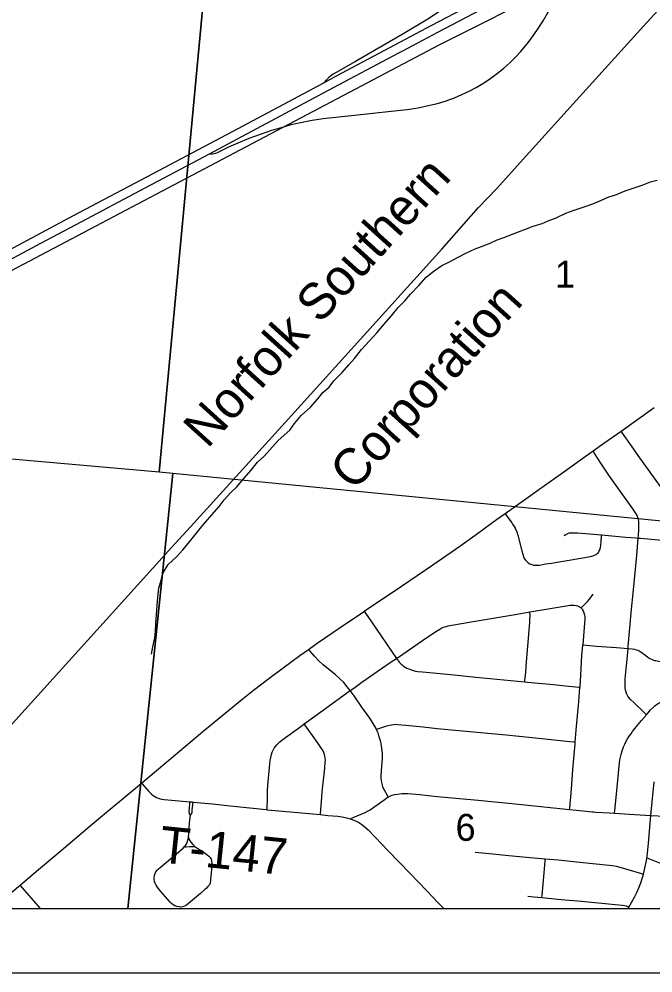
# Model space of a CAD drawing. Extents: x 831 to 1552, y 430 to 870.
# Drawn here: x 1297.11 to 1316.8, y 648.94 to 678.59 of the extents above; entities that cross this region are included whole.
import ezdxf

# ---------------------------------------------------------------- set-up
doc = ezdxf.new("R2010")
doc.units = 0
for name, color, linetype in [('GM_X_Corporation', 7, 'Continuous'), ('GM_X_County_Road', 7, 'Continuous'), ('GM_X_Interchange_Ramps', 7, 'Continuous'), ('GM_X_Interstate_Route', 7, 'Continuous'), ('GM_X_Minor_River', 7, 'Continuous'), ('GM_X_Rail_Line', 7, 'Continuous'), ('GM_X_Rail_Line_Text', 7, 'Continuous'), ('GM_X_Section_Text', 7, 'Continuous'), ('GM_X_State_Route', 7, 'Continuous'), ('GM_X_Township_Road', 7, 'Continuous'), ('GM_X_Township_Road_Text', 7, 'Continuous'), ('SH_Data', 7, 'Continuous')]:
    doc.layers.add(name, color=color, linetype=linetype)

msp = doc.modelspace()

# ---------------------------------------------------------------- linework, layer by layer
at = {"layer": 'GM_X_Corporation'}
msp.add_lwpolyline([(1250.766, 650.938), (1386.766, 650.938), (1386.766, 724.317)], dxfattribs=at)
for points in [[(1283.584, 686.544), (1303.37, 684.858), (1301.464, 664.502), (1281.807, 666.237)], [(1303.37, 684.858), (1323.531, 682.478), (1321.541, 662.548), (1301.887, 664.457), (1301.464, 664.502)], [(1280.498, 650.938), (1300.485, 650.938), (1301.887, 664.457), (1301.464, 664.502), (1281.807, 666.237)], [(1300.485, 650.938), (1320.907, 650.938), (1321.979, 662.503), (1321.541, 662.548), (1301.887, 664.457)]]:
    msp.add_lwpolyline(points, close=True, dxfattribs=at)
at = {"layer": 'GM_X_County_Road'}
msp.add_line((1315.814, 665.779), (1316.848, 666.513), dxfattribs=at)
for points in [[(1314.945, 665.163), (1315.28, 665.4), (1315.814, 665.779)], [(1312.208, 663.216), (1312.854, 663.671), (1313.258, 663.96), (1313.966, 664.464), (1314.622, 664.934), (1314.945, 665.163)], [(1307.827, 660.179), (1308.99, 660.963), (1309.967, 661.625), (1310.801, 662.203), (1311.351, 662.6), (1311.941, 663.027), (1312.208, 663.216)], [(1306.099, 658.994), (1306.369, 659.188), (1307.088, 659.676), (1307.807, 660.165), (1307.827, 660.179)], [(1300.908, 654.837), (1301.176, 655.06), (1301.506, 655.337), (1302.882, 656.497), (1304.028, 657.436), (1304.391, 657.722), (1304.865, 658.092), (1305.312, 658.426), (1305.832, 658.801), (1306.099, 658.994)], [(1297.137, 651.668), (1297.512, 651.984), (1298.414, 652.744), (1299.312, 653.508), (1299.703, 653.836), (1300.301, 654.33), (1300.908, 654.837)], [(1296.266, 650.938), (1296.609, 651.225), (1297.085, 651.624), (1297.137, 651.668)]]:
    msp.add_lwpolyline(points, dxfattribs=at)
at = {"layer": 'GM_X_Interchange_Ramps'}
msp.add_lwpolyline([(1316.766, 684.819), (1316.253, 684.266), (1315.369, 683.31), (1314.816, 682.723), (1314.381, 682.282), (1313.979, 681.895), (1313.477, 681.432), (1312.968, 680.979), (1312.401, 680.496), (1311.97, 680.143), (1311.432, 679.723), (1310.935, 679.352), (1310.48, 679.028), (1310.172, 678.821), (1309.805, 678.588), (1309.008, 678.109), (1307.562, 677.263), (1306.957, 676.925), (1306.87, 676.872), (1306.781, 676.807), (1306.736, 676.769), (1306.693, 676.73), (1306.652, 676.687), (1306.577, 676.607)], dxfattribs=at)
at = {"layer": 'GM_X_Interstate_Route'}
for points in [[(1296.221, 671.1), (1298.795, 672.482), (1301.269, 673.783), (1303.737, 675.096), (1306.577, 676.607), (1306.973, 676.818), (1309.934, 678.396), (1310.869, 678.886), (1311.642, 679.283), (1312.478, 679.693), (1313.096, 679.984), (1313.775, 680.291), (1314.453, 680.589), (1314.514, 680.616), (1315.029, 680.832), (1315.72, 681.109), (1316.416, 681.372), (1317.469, 681.748), (1318.641, 682.161), (1319.931, 682.613), (1320.991, 682.995), (1322.52, 683.559), (1323.315, 683.849), (1323.468, 683.902)], [(1308.905, 677.534), (1309.028, 677.6), (1310.125, 678.184), (1311.445, 678.879), (1312.057, 679.186), (1312.786, 679.534), (1313.002, 679.632)], [(1303.02, 674.4), (1303.6, 674.708), (1306.724, 676.375), (1308.905, 677.534)], [(1276.248, 660.164), (1276.827, 660.475), (1278.858, 661.553), (1281.437, 662.923), (1282.589, 663.534), (1284.234, 664.411), (1285.716, 665.197), (1288.513, 666.687), (1290.485, 667.742), (1290.978, 668.006), (1291.471, 668.27), (1291.819, 668.455), (1292.294, 668.707), (1293.889, 669.547), (1296.249, 670.798), (1297.783, 671.619), (1299.212, 672.373), (1300.69, 673.166), (1303.02, 674.4)]]:
    msp.add_lwpolyline(points, dxfattribs=at)
at = {"layer": 'GM_X_Minor_River'}
for points in [[(1305.524, 665.809), (1305.663, 666.019), (1305.871, 666.26), (1306.163, 666.522), (1306.387, 666.785), (1306.549, 666.981), (1306.741, 667.146), (1306.888, 667.341), (1307.149, 667.604), (1307.357, 667.837), (1307.527, 668.032), (1307.751, 668.318), (1307.997, 668.581), (1308.228, 668.829), (1308.444, 669.092), (1308.667, 669.355), (1308.883, 669.625), (1309.099, 669.828), (1309.276, 670.031), (1309.53, 670.309), (1309.754, 670.564), (1310.007, 670.759), (1310.244, 670.923), (1310.466, 671.034), (1310.756, 671.182), (1311.009, 671.316), (1311.284, 671.449), (1311.475, 671.515), (1311.749, 671.618), (1311.964, 671.722), (1312.17, 671.795), (1312.628, 671.972), (1312.849, 672.06), (1313.086, 672.149), (1313.36, 672.236), (1313.551, 672.317), (1313.795, 672.413), (1314.094, 672.554), (1314.33, 672.634), (1314.544, 672.708), (1314.734, 672.774), (1314.933, 672.847), (1315.208, 672.958), (1315.429, 673.061), (1315.62, 673.112), (1315.941, 673.245), (1316.254, 673.355), (1316.475, 673.428), (1316.727, 673.524), (1316.94, 673.582)], [(1301.226, 658.849), (1301.267, 659.076), (1301.323, 659.356), (1301.348, 659.56), (1301.359, 659.81), (1301.377, 660.053), (1301.396, 660.355), (1301.414, 660.62), (1301.448, 660.893), (1301.519, 661.142), (1301.582, 661.376), (1301.737, 661.632), (1302.012, 661.879), (1302.196, 662.089), (1302.357, 662.284), (1302.572, 662.546), (1302.733, 662.749), (1302.902, 662.951), (1303.094, 663.176), (1303.324, 663.439), (1303.477, 663.641), (1303.684, 663.866), (1303.875, 664.046), (1304.09, 664.308), (1304.32, 664.563), (1304.512, 664.811), (1304.719, 665.005), (1305.163, 665.485), (1305.524, 665.809)]]:
    msp.add_lwpolyline(points, dxfattribs=at)
at = {"layer": 'GM_X_Rail_Line'}
for points in [[(1261.527, 652.567), (1284.1, 664.037), (1310.179, 677.801), (1313.677, 679.557), (1320.635, 683.299), (1323.83, 685.434), (1326.948, 687.535)], [(1291.697, 650.938), (1294.966, 654.558), (1301.848, 662.157), (1302.434, 662.803), (1305.676, 666.376), (1310.245, 671.433), (1311.385, 672.727), (1311.952, 673.316), (1312.776, 674.235), (1314.625, 676.28), (1316.515, 678.363), (1317.75, 679.732), (1318.964, 681.068), (1319.334, 681.453), (1320.111, 682.215), (1320.633, 682.733), (1321.491, 683.396), (1322.009, 683.791), (1322.837, 684.376), (1324.039, 685.196), (1324.617, 685.605)]]:
    msp.add_lwpolyline(points, dxfattribs=at)
at = {"layer": 'GM_X_State_Route'}
for points in [[(1312.937, 677.87), (1313.086, 678.068), (1313.261, 678.324), (1313.392, 678.535), (1313.544, 678.805), (1313.772, 679.246), (1314.033, 679.763)], [(1303.02, 674.4), (1303.073, 674.396), (1303.12, 674.398), (1303.169, 674.406), (1303.222, 674.421), (1303.274, 674.441), (1303.629, 674.613), (1303.913, 674.74), (1304.258, 674.882), (1304.608, 675.013), (1304.962, 675.132), (1305.261, 675.221), (1305.603, 675.315), (1305.904, 675.381), (1306.213, 675.442), (1306.558, 675.497), (1307.532, 675.601), (1308.669, 675.723), (1309.164, 675.778), (1309.505, 675.829), (1309.87, 675.906), (1310.11, 675.966), (1310.347, 676.038), (1310.638, 676.143), (1310.867, 676.238), (1311.091, 676.343), (1311.31, 676.46), (1311.522, 676.587), (1311.729, 676.724), (1311.979, 676.907), (1312.172, 677.062), (1312.357, 677.227), (1312.534, 677.4), (1312.701, 677.583), (1312.9, 677.821), (1312.937, 677.87)], [(1276.248, 660.164), (1276.827, 660.475), (1278.858, 661.553), (1281.437, 662.923), (1282.589, 663.534), (1284.234, 664.411), (1285.716, 665.197), (1288.513, 666.687), (1290.485, 667.742), (1290.978, 668.006), (1291.471, 668.27), (1291.819, 668.455), (1292.294, 668.707), (1293.889, 669.547), (1296.249, 670.798), (1297.783, 671.619), (1299.212, 672.373), (1300.69, 673.166), (1303.02, 674.4)]]:
    msp.add_lwpolyline(points, dxfattribs=at)
at = {"layer": 'GM_X_Township_Road'}
for p, q in [((1316.742, 653.835), (1316.842, 654.882)), ((1297.771, 650.938), (1297.137, 651.668)), ((1316.03, 650.938), (1316.054, 650.979))]:
    msp.add_line(p, q, dxfattribs=at)
for points in [[(1317.442, 662.355), (1317.489, 662.868), (1317.504, 663.056), (1317.504, 663.184), (1317.499, 663.258), (1317.491, 663.325), (1317.477, 663.373), (1317.453, 663.439), (1317.43, 663.49), (1317.369, 663.594), (1317.265, 663.746), (1317.224, 663.802), (1316.719, 664.499), (1316.35, 665.024), (1316.136, 665.321), (1315.856, 665.719), (1315.814, 665.779)], [(1316.348, 662.455), (1316.354, 662.53), (1316.365, 662.716), (1316.369, 662.904), (1316.364, 662.968), (1316.352, 663.03), (1316.334, 663.092), (1316.31, 663.151), (1316.281, 663.207), (1316.182, 663.366), (1315.46, 664.375), (1315.184, 664.786), (1315.002, 665.074), (1314.945, 665.163)], [(1312.208, 663.216), (1312.243, 663.168), (1312.419, 662.924), (1312.445, 662.886), (1312.491, 662.814), (1312.52, 662.764), (1312.571, 662.652), (1312.603, 662.54), (1312.729, 662.056), (1312.784, 661.879), (1312.807, 661.822), (1312.84, 661.77), (1312.881, 661.724), (1312.929, 661.685), (1312.981, 661.652), (1313.038, 661.629), (1313.098, 661.614), (1313.16, 661.608), (1313.221, 661.61), (1313.283, 661.617), (1313.465, 661.649), (1313.649, 661.678), (1313.83, 661.707), (1314.135, 661.762), (1314.622, 661.841), (1314.804, 661.875), (1314.911, 661.897), (1314.97, 661.913), (1315.012, 661.931), (1315.043, 661.948), (1315.084, 661.981), (1315.109, 662.011), (1315.127, 662.036), (1315.156, 662.092), (1315.172, 662.162), (1315.185, 662.222), (1315.196, 662.345), (1315.207, 662.507), (1315.211, 662.554)], [(1314.05, 662.535), (1314.099, 662.566), (1314.14, 662.591), (1314.177, 662.605), (1314.208, 662.615), (1314.275, 662.621), (1314.337, 662.621), (1314.463, 662.614), (1315.087, 662.564), (1315.211, 662.554)], [(1315.211, 662.554), (1315.526, 662.528), (1315.965, 662.487), (1316.287, 662.459), (1316.348, 662.455)], [(1316.035, 659.024), (1316.039, 659.079), (1316.139, 660.246), (1316.189, 660.739), (1316.304, 661.912), (1316.348, 662.455)], [(1316.348, 662.455), (1316.414, 662.451), (1316.981, 662.4), (1317.442, 662.355)], [(1314.574, 660.29), (1314.654, 660.367), (1314.772, 660.486), (1314.823, 660.541), (1314.864, 660.593), (1314.899, 660.639), (1314.947, 660.707)], [(1312.984, 660.157), (1313.615, 660.267), (1314.105, 660.349), (1314.228, 660.364), (1314.291, 660.368), (1314.354, 660.367), (1314.418, 660.356), (1314.46, 660.345), (1314.508, 660.33), (1314.543, 660.311), (1314.574, 660.29)], [(1314.574, 660.29), (1314.594, 660.267), (1314.621, 660.227), (1314.637, 660.197), (1314.648, 660.165), (1314.661, 660.13), (1314.676, 660.066), (1314.684, 660.002), (1314.687, 659.937), (1314.679, 659.81), (1314.627, 659.138)], [(1307.827, 660.179), (1307.87, 660.117), (1308.057, 659.847), (1308.831, 658.713)], [(1308.831, 658.713), (1309.033, 658.848), (1309.646, 659.267), (1310.055, 659.548), (1310.178, 659.626), (1310.244, 659.66), (1310.296, 659.681), (1310.351, 659.7), (1310.438, 659.725), (1310.495, 659.736), (1310.554, 659.75), (1311.16, 659.849), (1312.585, 660.087), (1312.984, 660.157)], [(1312.824, 657.983), (1312.828, 658.023), (1312.852, 658.288), (1312.878, 658.609), (1312.914, 659.097), (1312.975, 659.829), (1312.98, 659.934), (1312.985, 660.048), (1312.984, 660.157)], [(1314.537, 657.814), (1314.539, 657.84), (1314.561, 658.196), (1314.6, 658.808), (1314.627, 659.138)], [(1314.627, 659.138), (1315.051, 659.097), (1315.67, 659.05), (1316.035, 659.024)], [(1307.399, 657.715), (1307.305, 657.831), (1307.194, 657.962), (1307.067, 658.087), (1306.93, 658.213), (1306.556, 658.514), (1306.42, 658.642), (1306.286, 658.781), (1306.141, 658.947), (1306.099, 658.994)], [(1316.603, 656.959), (1316.541, 657.02), (1316.496, 657.063), (1316.227, 657.32), (1316.102, 657.452), (1316.06, 657.5), (1316.026, 657.544), (1315.993, 657.605), (1315.968, 657.666), (1315.954, 657.725), (1315.942, 657.791), (1315.939, 657.868), (1315.939, 657.965), (1315.944, 658.08), (1315.977, 658.392), (1315.998, 658.577), (1316.035, 659.024)], [(1316.035, 659.024), (1316.164, 659.009), (1316.23, 658.997), (1316.283, 658.985), (1316.334, 658.968), (1316.374, 658.95), (1316.411, 658.931), (1316.459, 658.9), (1316.512, 658.861), (1316.583, 658.802), (1316.649, 658.75), (1316.707, 658.715), (1316.764, 658.688), (1316.805, 658.67), (1316.858, 658.653), (1316.898, 658.644), (1316.976, 658.633), (1317.073, 658.622), (1317.097, 658.62)], [(1307.399, 657.715), (1307.506, 657.791), (1307.762, 657.976), (1308.367, 658.396), (1308.673, 658.608), (1308.831, 658.713)], [(1308.831, 658.713), (1308.897, 658.632), (1308.934, 658.589), (1308.985, 658.535), (1309.01, 658.512), (1309.058, 658.475), (1309.101, 658.445), (1309.16, 658.413), (1309.218, 658.388), (1309.276, 658.364), (1309.358, 658.337), (1309.425, 658.321), (1309.497, 658.309), (1309.639, 658.295), (1310.627, 658.201), (1311.305, 658.13), (1312.824, 657.983)], [(1312.824, 657.983), (1312.911, 657.975), (1313.713, 657.898), (1314.083, 657.86), (1314.5, 657.818), (1314.537, 657.814)], [(1305.965, 656.677), (1306.554, 657.106), (1306.754, 657.249), (1307.399, 657.715)], [(1308.215, 656.507), (1308.203, 656.533), (1308.139, 656.642), (1308.077, 656.741), (1308.003, 656.852), (1307.76, 657.198), (1307.516, 657.549), (1307.399, 657.715)], [(1314.39, 656.114), (1314.422, 656.485), (1314.501, 657.37), (1314.537, 657.814)], [(1316.603, 656.959), (1316.652, 657.018), (1316.732, 657.113), (1316.819, 657.202), (1316.866, 657.242), (1316.916, 657.279), (1316.969, 657.311), (1317.058, 657.36), (1317.132, 657.396), (1317.204, 657.425), (1317.267, 657.441), (1317.315, 657.453), (1317.438, 657.471), (1317.568, 657.478), (1317.686, 657.473), (1317.93, 657.456), (1318.235, 657.429)], [(1315.611, 653.9), (1315.62, 653.991), (1315.669, 654.495), (1315.718, 654.927), (1315.767, 655.483), (1315.786, 655.606), (1315.814, 655.727), (1315.851, 655.845), (1315.891, 655.964), (1315.929, 656.048), (1315.973, 656.143), (1316.018, 656.213), (1316.068, 656.296), (1316.123, 656.374), (1316.17, 656.444), (1316.246, 656.539), (1316.454, 656.779), (1316.603, 656.959)], [(1304.817, 654.011), (1304.818, 654.053), (1304.825, 654.355), (1304.83, 654.581), (1304.841, 654.778), (1304.87, 655.09), (1304.9, 655.438), (1304.911, 655.538), (1304.927, 655.63), (1304.947, 655.724), (1304.97, 655.804), (1305, 655.866), (1305.036, 655.927), (1305.074, 655.98), (1305.112, 656.026), (1305.166, 656.079), (1305.211, 656.121), (1305.27, 656.171), (1305.46, 656.31), (1305.903, 656.632), (1305.965, 656.677)], [(1306.469, 653.857), (1306.473, 653.894), (1306.505, 654.251), (1306.53, 654.562), (1306.611, 655.306), (1306.624, 655.491), (1306.625, 655.55), (1306.621, 655.614), (1306.612, 655.673), (1306.597, 655.732), (1306.577, 655.789), (1306.552, 655.844), (1306.488, 655.949), (1306.384, 656.103), (1305.987, 656.647), (1305.965, 656.677)], [(1308.215, 656.507), (1308.252, 656.52), (1308.44, 656.586), (1308.531, 656.613), (1308.62, 656.638), (1308.682, 656.651), (1308.745, 656.659), (1308.803, 656.665), (1308.872, 656.662), (1309.121, 656.641), (1309.662, 656.586), (1310.101, 656.54), (1310.77, 656.475), (1312.246, 656.338), (1313.452, 656.216), (1314.213, 656.135), (1314.345, 656.119), (1314.39, 656.114)], [(1308.581, 654.404), (1308.552, 654.454), (1308.458, 654.614), (1308.416, 654.713), (1308.398, 654.77), (1308.379, 654.854), (1308.364, 654.978), (1308.361, 655.077), (1308.376, 655.356), (1308.396, 655.611), (1308.398, 655.752), (1308.391, 655.843), (1308.371, 655.999), (1308.344, 656.125), (1308.299, 656.281), (1308.272, 656.365), (1308.24, 656.454), (1308.215, 656.507)], [(1314.217, 654.016), (1314.22, 654.059), (1314.269, 654.649), (1314.319, 655.26), (1314.384, 656.054), (1314.39, 656.114)], [(1300.908, 654.837), (1300.93, 654.813), (1301.138, 654.58), (1301.179, 654.535), (1301.224, 654.492), (1301.272, 654.454), (1301.323, 654.421), (1301.377, 654.393), (1301.434, 654.37), (1301.493, 654.353), (1301.614, 654.332), (1302.304, 654.268), (1302.418, 654.257)], [(1307.394, 653.728), (1307.486, 653.767), (1307.733, 653.868), (1307.866, 653.927), (1307.958, 653.976), (1308.015, 654.008), (1308.131, 654.085), (1308.481, 654.342), (1308.534, 654.378), (1308.581, 654.404)], [(1308.581, 654.404), (1308.648, 654.441), (1308.698, 654.458), (1308.774, 654.483), (1308.866, 654.498), (1308.997, 654.513), (1309.185, 654.51), (1309.56, 654.481), (1310.095, 654.421), (1311.375, 654.305), (1312.523, 654.194), (1314.217, 654.016)], [(1302.432, 653.837), (1302.408, 653.883), (1302.399, 653.917), (1302.398, 653.94), (1302.397, 653.964), (1302.401, 654.06), (1302.414, 654.209), (1302.418, 654.257)], [(1302.418, 654.257), (1302.481, 654.251), (1302.518, 654.248), (1303.115, 654.19), (1303.672, 654.132), (1304.785, 654.014), (1304.817, 654.011)], [(1302.432, 653.837), (1302.46, 653.871), (1302.471, 653.89), (1302.477, 653.907), (1302.482, 653.93), (1302.485, 653.956), (1302.49, 654.001), (1302.51, 654.174), (1302.518, 654.248)], [(1302.369, 653.148), (1302.379, 653.27), (1302.407, 653.598), (1302.432, 653.837)], [(1304.817, 654.011), (1305.538, 653.941), (1306.109, 653.89), (1306.469, 653.857)], [(1306.469, 653.857), (1306.703, 653.835), (1307.013, 653.805), (1307.199, 653.778), (1307.322, 653.751), (1307.394, 653.728)], [(1314.217, 654.016), (1314.432, 653.993), (1314.912, 653.948), (1314.953, 653.944)], [(1314.953, 653.944), (1315.035, 653.937), (1315.451, 653.909), (1315.611, 653.9)], [(1315.611, 653.9), (1316.073, 653.873), (1316.742, 653.835)], [(1316.616, 652.519), (1316.621, 652.554), (1316.671, 652.969), (1316.742, 653.835)], [(1316.742, 653.835), (1317.627, 653.785), (1318.616, 653.731), (1318.844, 653.727), (1319.115, 653.731), (1319.718, 653.738), (1320.19, 653.739)], [(1307.394, 653.728), (1307.456, 653.707), (1307.566, 653.662), (1307.685, 653.598), (1307.799, 653.521), (1307.958, 653.382), (1308.184, 653.147), (1308.571, 652.742), (1309.26, 652.024), (1309.776, 651.486), (1310.124, 651.13), (1310.307, 650.938)], [(1302.241, 652.852), (1302.259, 652.868), (1302.303, 652.931), (1302.33, 652.984), (1302.346, 653.035), (1302.363, 653.103), (1302.369, 653.148)], [(1302.369, 653.148), (1302.389, 653.09), (1302.424, 653.037), (1302.456, 652.992), (1302.497, 652.939), (1302.537, 652.897), (1302.58, 652.862)], [(1302.58, 652.862), (1302.599, 652.846), (1302.661, 652.805), (1302.793, 652.72), (1302.897, 652.651), (1302.956, 652.609), (1303.003, 652.57), (1303.044, 652.521), (1303.073, 652.474), (1303.089, 652.419), (1303.097, 652.348), (1303.097, 652.284), (1303.077, 652.034), (1303.058, 651.848), (1303.054, 651.797), (1303.042, 651.737), (1303.022, 651.68), (1302.977, 651.621), (1302.929, 651.572), (1302.884, 651.528), (1302.74, 651.409), (1302.314, 651.046), (1302.252, 651.011), (1302.187, 650.993), (1302.132, 650.984), (1302.077, 650.987), (1302.007, 650.999), (1301.948, 651.021), (1301.892, 651.058), (1301.843, 651.096), (1301.799, 651.14), (1301.515, 651.472), (1301.398, 651.618), (1301.364, 651.67), (1301.335, 651.725), (1301.315, 651.783), (1301.303, 651.844), (1301.303, 651.906), (1301.313, 651.968), (1301.332, 652.027), (1301.361, 652.081), (1301.398, 652.131), (1301.441, 652.177), (1301.487, 652.219), (1302.203, 652.818), (1302.241, 652.852)], [(1302.241, 652.852), (1302.303, 652.858), (1302.418, 652.868), (1302.482, 652.87), (1302.547, 652.865), (1302.58, 652.862)], [(1311.276, 652.695), (1311.828, 652.639), (1312.327, 652.592), (1312.879, 652.539), (1313.458, 652.486)], [(1313.352, 651.281), (1313.358, 651.34), (1313.421, 652.046), (1313.453, 652.423), (1313.458, 652.486)], [(1313.458, 652.486), (1313.873, 652.448), (1314.43, 652.39), (1315.044, 652.33), (1315.345, 652.301), (1315.549, 652.274), (1315.661, 652.255), (1315.777, 652.228), (1316.026, 652.153), (1316.451, 652.028), (1316.514, 652.011)], [(1316.514, 652.011), (1316.556, 652.19), (1316.601, 652.417), (1316.616, 652.519)], [(1316.616, 652.519), (1316.694, 652.487), (1316.955, 652.379), (1317.108, 652.318), (1317.225, 652.28), (1317.313, 652.26), (1317.488, 652.233), (1317.728, 652.21)], [(1316.054, 650.979), (1316.24, 651.317), (1316.303, 651.441), (1316.37, 651.587), (1316.431, 651.737), (1316.494, 651.937), (1316.514, 652.011)], [(1312.916, 651.319), (1313.1, 651.304), (1313.352, 651.281)], [(1313.352, 651.281), (1313.956, 651.225), (1314.583, 651.168), (1315.626, 651.067), (1315.854, 651.042), (1315.917, 651.032), (1315.971, 651.021), (1316.02, 650.999), (1316.054, 650.979)]]:
    msp.add_lwpolyline(points, dxfattribs=at)
at = {"layer": 'SH_Data'}
for p, q in [((1250.766, 650.938), (1386.766, 650.938)), ((1248.766, 648.938), (1388.766, 648.938))]:
    msp.add_line(p, q, dxfattribs=at)

# ---------------------------------------------------------------- texts
at = {"layer": 'GM_X_Rail_Line_Text'}
for s, rotation, p in [('Norfolk Southern', 47.9036, (1302.961, 665.212)), ('Corporation', 48.0126, (1307.518, 663.885))]:
    msp.add_text(s, height=1.13258, rotation=rotation, dxfattribs=at).set_placement(p)
at = {"layer": 'GM_X_Section_Text'}
for s, p in [('1', (1313.762, 670.243)), ('6', (1310.671, 653.043))]:
    msp.add_text(s, height=0.837, rotation=0, dxfattribs=at).set_placement(p)
at = {"layer": 'GM_X_Township_Road_Text'}
msp.add_text('T-147', height=1.1364, rotation=354.1319, dxfattribs=at).set_placement((1301.433, 652.38))

doc.saveas('drawing.dxf')
